Omron CX-Programmer project NuevoProyecto (CX-Programmer 9.50)

# PLC NewPLC1: CP1L-E EM

## Program P12_3 (cyclic task 0)
Local symbols
Etapa_0 10.00 BOOL
Etapa_1 10.01 BOOL
Etapa_10 10.10 BOOL
Etapa_11 10.11 BOOL
Etapa_12 10.12 BOOL
Etapa_13 10.13 BOOL
Etapa_2 10.02 BOOL
Etapa_3 10.03 BOOL
F1 0.01 BOOL
F2 0.02 BOOL
F3 0.03 BOOL
F4 0.04 BOOL
P 0.00 BOOL
Pm 15.00 BOOL
Rd1 100.00 BOOL
Rd2 100.02 BOOL
Ri1 100.01 BOOL
Ri2 100.03 BOOL

### Section Sección1_Programa_principal
; Etapas 0 ... 3 más Etapas 10 ... 13

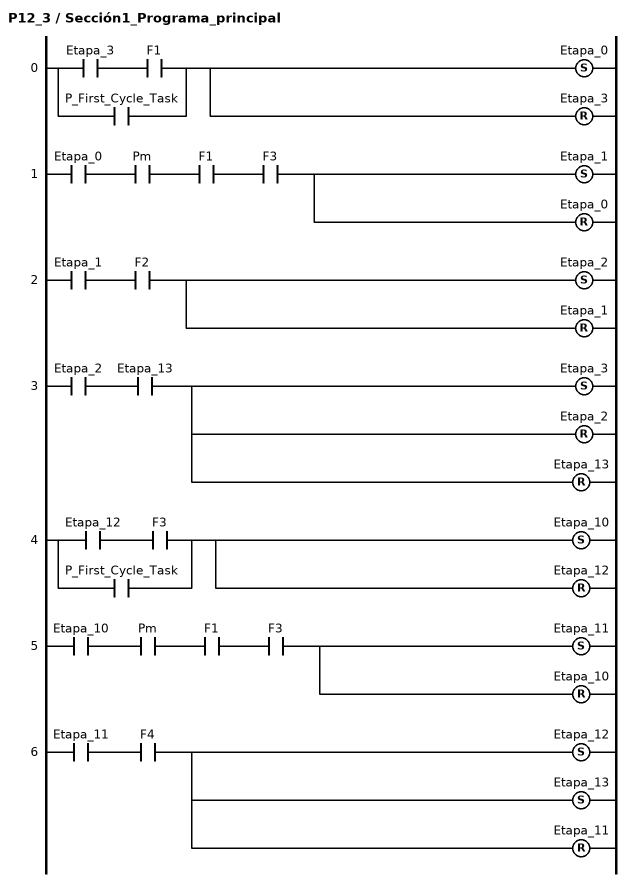
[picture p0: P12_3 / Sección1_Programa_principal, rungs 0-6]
; rung 0
LD Etapa_3
AND F1
OR P_First_Cycle_Task
SET Etapa_0
RSET Etapa_3
; rung 1
LD Etapa_0
AND Pm
AND F1
AND F3
SET Etapa_1
RSET Etapa_0
; rung 2
LD Etapa_1
AND F2
SET Etapa_2
RSET Etapa_1
; rung 3
LD Etapa_2
AND Etapa_13
SET Etapa_3
RSET Etapa_2
RSET Etapa_13
; rung 4
LD Etapa_12
AND F3
OR P_First_Cycle_Task
SET Etapa_10
RSET Etapa_12
; rung 5
LD Etapa_10
AND Pm
AND F1
AND F3
SET Etapa_11
RSET Etapa_10
; rung 6
LD Etapa_11
AND F4
SET Etapa_12
SET Etapa_13
RSET Etapa_11

### Section Sección2_Paro_memorizado

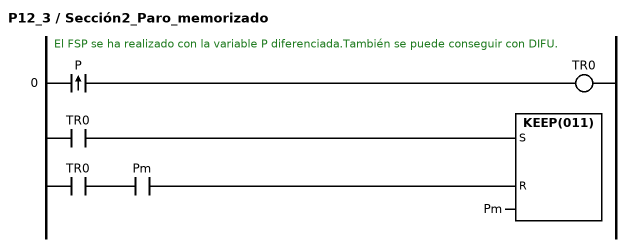
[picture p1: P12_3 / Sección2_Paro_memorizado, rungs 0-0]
; rung 0: El FSP se ha realizado con la variable P diferenciada.También se puede conseguir con DIFU.
@LD P
OUT TR0
LD TR0
AND Pm
KEEP(011) Pm

### Section Sección3_Salidas
; Salidas

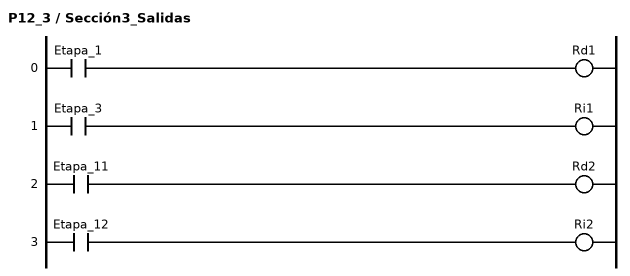
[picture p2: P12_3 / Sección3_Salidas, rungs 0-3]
; rung 0
LD Etapa_1
OUT Rd1
; rung 1
LD Etapa_3
OUT Ri1
; rung 2
LD Etapa_11
OUT Rd2
; rung 3
LD Etapa_12
OUT Ri2

### Section Sección4_END
; rung 0
END(001)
